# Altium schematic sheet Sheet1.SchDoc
size A4
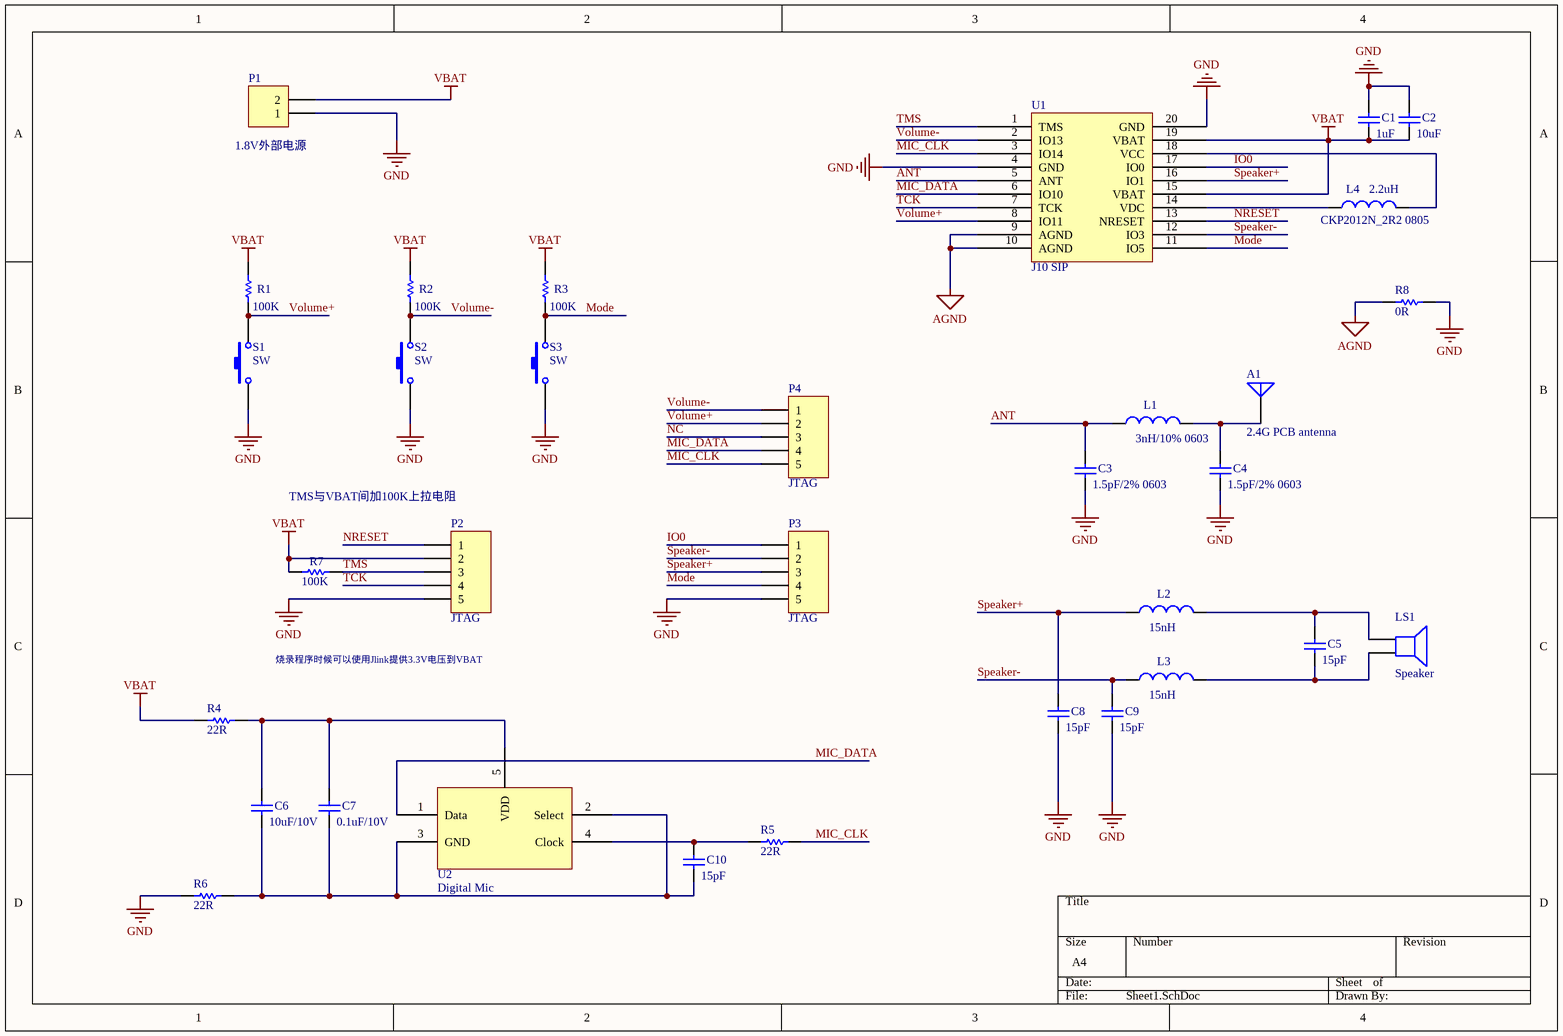
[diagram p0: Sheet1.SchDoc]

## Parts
A1  2.4G PCB antenna  [PIN1]
C1  1uF  [0603_C]
C2  10uF  [0603_C]
C3  value 1.5pF/2% 0603  [0603_C]  (hidden comment: 1.5pF/2%)
C4  value 1.5pF/2% 0603  [0603_C]  (hidden comment: 1.5pF/2%)
C5  15pF  [0603_C]
C6  value 10uF/10V  [0603_C]  (hidden comment: 10uF)
C7  value 0.1uF/10V  [0603_C]  (hidden comment: 0.1uF)
C8  15pF  [0603_C]
C9  15pF  [0603_C]
C10  value 15pF  [0603_C]  (hidden comment: 0.1uF)
L1  value 3nH/10% 0603  [0603_L]  (hidden comment: 3nH/10%)
L2  value 15nH  [0603_L]  (hidden comment: 15nF)
L3  15nH  [0603_L]
L4  CKP2012N_2R2 0805  value 2.2uH  [0805_L]
LS1  Speaker  [PIN2]
P1  1.8V外部电源  [HDR1X2]
P2  JTAG  [HDR1X5]
P3  JTAG  [HDR1X5]
P4  JTAG  [HDR1X5]
R1  100K  [0603_R]
R2  100K  [0603_R]
R3  100K  [0603_R]
R4  22R  [0603_R]
R5  22R  [0603_R]
R6  22R  [0603_R]
R7  100K  [0603_R]
R8  value 0R  [0603_R]  (hidden comment: 22R)
S1  SW  [S-C&K-RS-282G05A3-SM RT]
S2  SW  [S-C&K-RS-282G05A3-SM RT]
S3  SW  [S-C&K-RS-282G05A3-SM RT]
U1  J10 SIP  [JIP]
U2  Digital Mic  [SPH0641LM4H]

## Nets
AGND: R8.2 U1.9(AGND) U1.10(AGND)
GND: C1.2 C2.2 C3.1 C4.1 C8.1 C9.1 P1.1 P2.5 P3.5 R6.2 R8.1 S1.1 S2.1 S3.1 U1.4(GND) U1.20(GND)
VBAT: C1.1 C2.1 P1.2 P2.2 R1.2 R2.2 R3.2 R4.2 R7.2 U1.15(VBAT) U1.19(VBAT)
ANT: C3.2 L1.1 U1.5(ANT)
IO0: P3.1 U1.17(IO0)
MIC_CLK: P4.5 R5.1 U1.3(IO14)
MIC_DATA: P4.4 U1.6(IO10) U2.1(Data)
Mode: P3.4 R3.1 S3.2 U1.11(IO5)
NC: P4.3
NRESET: P2.1 U1.13(NRESET)
Speaker+: C8.2 L2.1 P3.3 U1.16(IO1)
Speaker-: C9.2 L3.1 P3.2 U1.12(IO3)
TCK: P2.4 U1.7(TCK)
TMS: P2.3 R7.1 U1.1(TMS)
Volume+: P4.2 R1.1 S1.2 U1.8(IO11)
Volume-: P4.1 R2.1 S2.2 U1.2(IO13)
NetA1_1: A1.1(A) C4.2 L1.2
NetC5_1: C5.1 L3.2 LS1.2
NetC5_2: C5.2 L2.2 LS1.1
NetC6_1: C6.1 C7.1 C10.1 R6.1 U2.2(Select) U2.3(GND)
NetC6_2: C6.2 C7.2 R4.1 U2.5(VDD)
NetC10_2: C10.2 R5.2 U2.4(Clock)
NetL4_1: L4.1 U1.14(VDC)
NetL4_2: L4.2 U1.18(VCC)

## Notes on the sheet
- TMS与VBAT间加100K上拉电阻
- 烧录程序时候可以使用Jlink提供3.3V电压到VBAT

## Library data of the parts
A1 = Antenna: Generic Antenna
C1-C10 = Cap: Capacitor
L1-L4 = Inductor: Code_IEC: 1005
LS1 = Speaker: Loudspeaker
P1 = Header 2: Header, 2-Pin
P2-P4 = Header 5: Header, 5-Pin
R1-R8 = Res1: Resistor
S1-S3 = SW-PB: Switch
U1 U2 = Component_1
